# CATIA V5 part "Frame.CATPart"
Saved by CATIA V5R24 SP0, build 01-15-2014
Part number: Frame
Bounding box of the stored display mesh (mm): x 32.749 to 67.749, y -45 to 45, z -14.5 to 14.5
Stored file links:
  \\cdl-main\FTPSERVER\Minsik\2016\2\Frame.CATPart
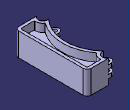
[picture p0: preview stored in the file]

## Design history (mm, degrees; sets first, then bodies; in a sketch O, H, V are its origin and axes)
Set1
  Sketch1 on xy-plane, origin (0, 0, 0), H (1, 0, 0), V (0, 1, 0)
    arc A1 centre (0, 0) radius 50 from (34.3174, -36.3636) to (34.3174, 36.3636) ccw
    line L1 (37.7492, 45) -> (62.7492, 45)
    line L2 (67.7492, 40) -> (67.7492, -40)
    line L3 (62.7492, -45) -> (37.7492, -45)
    arc A2 centre (62.7492, -40) radius 5 from (62.7492, -45) to (67.7492, -40) ccw
    arc A3 centre (62.7492, 40) radius 5 from (62.7492, 45) to (67.7492, 40) cw
    arc A4 centre (37.7492, 40) radius 5 from (37.7492, 45) to (34.3174, 36.3636) ccw
    point P9 (37.7492, 40)
    arc A5 centre (37.7492, -40) radius 5 from (34.3174, -36.3636) to (37.7492, -45) ccw
    radius A1 = 50
    distance L1 H = 45
    radius A2 = 5
    radius A3 = 5
    radius A4 = 5
    radius A5 = 5
    distance L2 P9 = 30
    horizontal: L1 H, L3 H
    vertical: L2 V
    symmetry: L1 L3 H
    tangency: A2 L3, A2 L2, A3 L1, A3 L2, A4 L1, A4 A1, A5 A1, A5 L3
Body1 (main body)
  Pad1: profile Sketch1, direction (0, 0, 1), length 14.5
  Sketch2 on end face of Pad1, origin (0, 0, 14.5), H (1, 0, 0), V (0, 1, 0)
    circle A1 centre (37.7492, 40) radius 6
    circle A2 centre (37.7492, -40) radius 6
    reference projected arc E1 centre (37.7492, 40) radius 5 from (37.7492, 45) to (34.3174, 36.3636) ccw from edge [face of Pad1 from Sketch1.A4 | end face of Pad1]
    reference projected arc E2 centre (37.7492, -40) radius 5 from (34.3174, -36.3636) to (37.7492, -45) ccw from edge [face of Pad1 from Sketch1.A5 | end face of Pad1]
    radius A2 = 6
    radius A1 = 6
    concentricity: A1 E1, A2 E2
  Pocket1: profile Sketch2, direction (0, 0, -1), length 7
  Sketch3 on xy-plane, origin (0, 0, 0), H (1, 0, 0), V (0, 1, 0)
    point P1 (37.7492, -20)
    line L1 (37.7492, -20) -> (54.5791, -20)
    line L2 (54.5791, -20) -> (54.5791, -30)
    line L3 (54.5791, -30) -> (37.7492, -30)
    arc A1 centre (37.7492, -25) radius 5 from (37.7492, -30) to (37.7492, -20) cw
    point P5 (37.7492, -25)
    point P6 (37.7492, -20)
    reference projected line E1 (37.7492, -45) -> (62.7492, -45) from edge [face of Pad1 from Sketch1.L3 | end face of Pad1]
    reference projected line E2 (67.7492, -40) -> (67.7492, 40) from edge [face of Pad1 from Sketch1.L2 | end face of Pad1]
    distance P5 E1 = 20
    radius A1 = 5
    distance P5 E2 = 30
    horizontal: L1 H, L3 H
    vertical: L2 V
    tangency: A1 L1, A1 L3
    coincidence: P1 P6
  Pad2: profile Sketch3, direction (0, 0, 1), length 7.5
  Sketch4 on start face of Pad1, origin (0, 0, 0), H (1, 0, 0), V (0, -1, 0)
    circle A1 centre (37.7492, 40) radius 6
    circle A2 centre (37.7492, -40) radius 6
    reference projected arc E1 centre (37.7492, 40) radius 5 from (37.7492, 45) to (34.3174, 36.3636) ccw from edge [start face of Pad1 | face of Pad1 from Sketch1.A5]
    reference projected arc E2 centre (37.7492, -40) radius 5 from (34.3174, -36.3636) to (37.7492, -45) ccw from edge [start face of Pad1 | face of Pad1 from Sketch1.A4]
    circle A3 centre (37.7492, 25) radius 6
    reference projected arc E3 centre (37.7492, 25) radius 5 from (37.7492, 30) to (37.7492, 20) ccw from edge [start face of Pad2 | face of Pad2 from Sketch3.A1]
    radius A1 = 6
    radius A2 = 6
    radius A3 = 6
    concentricity: A1 E1, A2 E2, A3 E3
  Pocket2: profile Sketch4, direction (0, 0, 1), length 3
  Sketch5 on end face of Pad1, origin (0, 0, 14.5), H (1, 0, 0), V (0, 1, 0)
  Pocket3: profile Sketch5, direction (0, 0, -1), length 10
  Sketch6 on end face of Pocket1, origin (37.4808, 40.3986, 7.5), H (1, 0, 0), V (0, 1, 0)
    point P1 (0.2684, -0.3986)
    reference projected arc E1 centre (0.2684, -0.3986) radius 5 from (0.2684, 4.6014) to (-3.1634, -4.0349) ccw from edge [face of Pad1 from Sketch1.A4 | end face of Pocket1]
    concentricity: E1 P1
  Hole1: placed by Sketch6, at (37.7492, 40, 7.5) direction (0, 0, -1), diameter 5, through (limit type 6)
  Sketch7 on end face of Pocket1, origin (36.3741, -40.4689, 7.5), H (1, 0, 0), V (0, 1, 0)
    point P1 (1.375, 0.4689)
    reference projected arc E1 centre (1.375, 0.4689) radius 5 from (-2.0567, 4.1053) to (1.375, -4.5311) ccw from edge [face of Pad1 from Sketch1.A5 | end face of Pocket1]
    concentricity: E1 P1
  Hole2: placed by Sketch7, at (37.7492, -40, 7.5) direction (0, 0, -1), diameter 5, through (limit type 6)
  Sketch8 on end face of Pad2, origin (38.5162, -25.0933, 7.5), H (1, 0, 0), V (0, 1, 0)
    point P1 (-0.767, 0.0933)
    reference projected arc E1 centre (-0.767, 0.0933) radius 5 from (-0.767, 5.0933) to (-0.767, -4.9067) ccw from edge [face of Pad2 from Sketch3.A1 | end face of Pad2]
    concentricity: E1 P1
  Hole3: placed by Sketch8, at (37.7492, -25, 7.5) direction (0, 0, -1), diameter 5, through (limit type 6)
  Mirror1: of the body so far, about xy-plane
